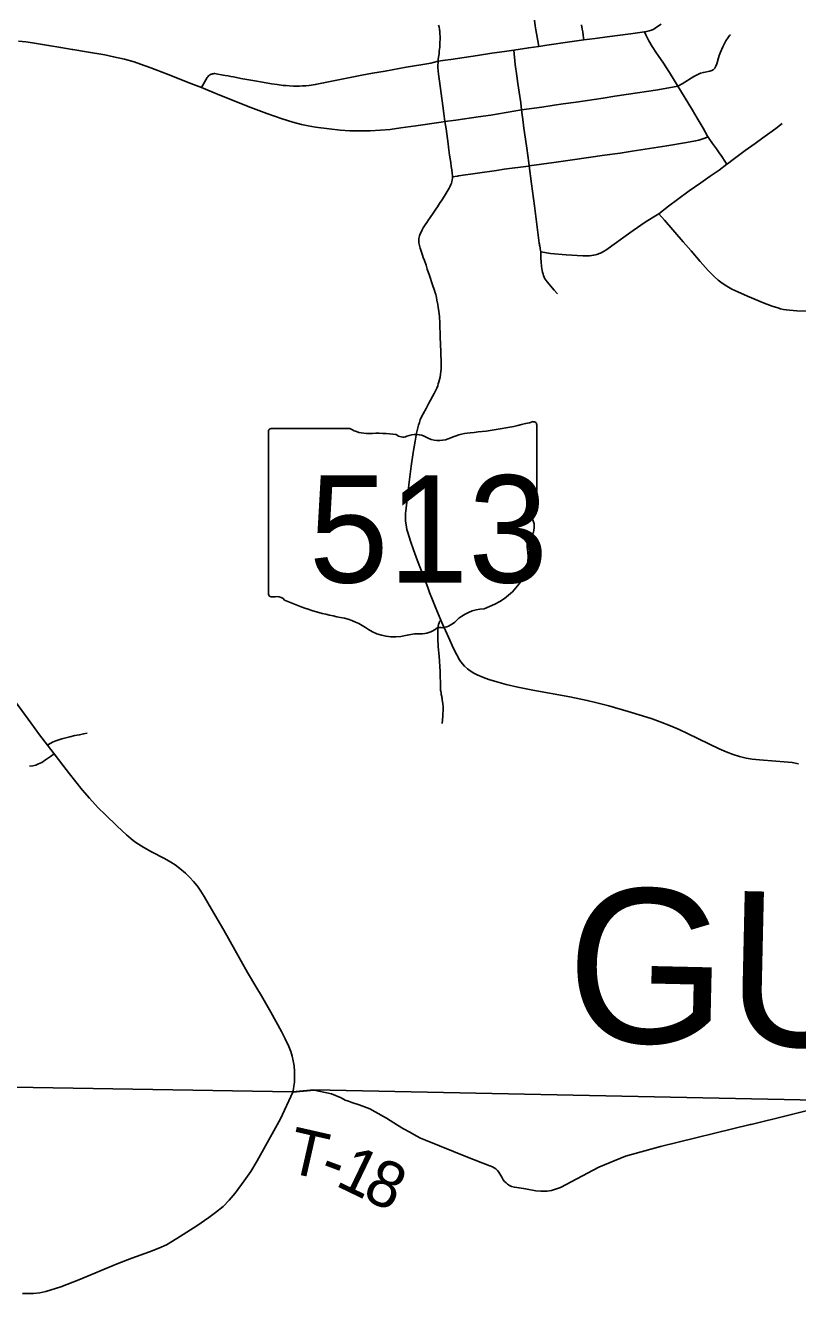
# Model space of a CAD drawing. Extents: x -10 to 158, y 8 to 33.
# Drawn here: x 149.672 to 150.622, y 29.874 to 31.433 of the extents above; entities that cross this region are included whole.
import ezdxf

# ---------------------------------------------------------------- set-up
doc = ezdxf.new("R2010")
doc.units = 0
for name, color, linetype in [('GM_X_City_Street', 7, 'Continuous'), ('GM_X_County_Road', 7, 'Continuous'), ('GM_X_County_Text', 7, 'Continuous'), ('GM_X_State_Location', 7, 'Continuous'), ('GM_X_State_Route', 7, 'Continuous'), ('GM_X_State_Shield', 7, 'Continuous'), ('GM_X_Township_Road', 7, 'Continuous'), ('GM_X_Township_Road_Text', 7, 'Continuous'), ('GM_X_Township_Text', 7, 'Continuous')]:
    doc.layers.add(name, color=color, linetype=linetype)

msp = doc.modelspace()

# ---------------------------------------------------------------- linework, layer by layer
at = {"layer": 'GM_X_City_Street'}
for points in [[(150.3034, 31.4071), (150.3022, 31.4138), (150.2999, 31.4276), (150.2992, 31.4322), (150.2982, 31.4391)], [(150.2726, 31.4023), (150.2912, 31.4054), (150.3034, 31.4071), (150.3133, 31.4086), (150.3416, 31.4126), (150.359, 31.415), (150.373, 31.4169), (150.3877, 31.4188), (150.4161, 31.4224), (150.4277, 31.424), (150.4334, 31.4249), (150.4344, 31.425), (150.4392, 31.4261), (150.4421, 31.427), (150.4448, 31.4283), (150.4484, 31.4305), (150.4538, 31.4345)], [(150.356, 31.4334), (150.3569, 31.4284), (150.3575, 31.4251), (150.3582, 31.4203), (150.3586, 31.4178), (150.359, 31.415)], [(150.5347, 31.2623), (150.5323, 31.266), (150.5286, 31.2716), (150.5276, 31.2731), (150.5262, 31.2751), (150.522, 31.2812), (150.5173, 31.2877), (150.5127, 31.2943), (150.5117, 31.2958), (150.511, 31.2969), (150.5056, 31.3067), (150.4984, 31.319), (150.4926, 31.3285), (150.4822, 31.3454), (150.4745, 31.3581), (150.4641, 31.3751), (150.456, 31.3876), (150.4483, 31.3988), (150.4428, 31.4071), (150.4388, 31.414), (150.4369, 31.4179), (150.4352, 31.4213), (150.4334, 31.4249)], [(150.4745, 31.3581), (150.4797, 31.3612), (150.494, 31.37), (150.4989, 31.3726), (150.5024, 31.374), (150.506, 31.3751), (150.5139, 31.3767), (150.5151, 31.3771), (150.5163, 31.3775), (150.5172, 31.378), (150.5179, 31.3784), (150.5187, 31.379), (150.5193, 31.3796), (150.5198, 31.3803), (150.5205, 31.3811), (150.5209, 31.3818), (150.5213, 31.3827), (150.5223, 31.3857), (150.5252, 31.3959), (150.5268, 31.4), (150.5297, 31.4067), (150.5336, 31.4139), (150.5362, 31.4181), (150.5382, 31.4205), (150.5391, 31.4213)], [(149.9154, 31.3718), (149.9179, 31.3714), (149.9216, 31.3708), (149.9247, 31.3702), (149.928, 31.3696), (149.937, 31.3677), (149.9542, 31.3649), (149.9639, 31.363), (149.9749, 31.3612), (149.9818, 31.3601), (149.989, 31.3592), (149.9927, 31.3589), (149.997, 31.3586), (150.0018, 31.3583), (150.0063, 31.3582), (150.0094, 31.3582), (150.0131, 31.3584), (150.0169, 31.3587), (150.0212, 31.3592), (150.0286, 31.3602), (150.0389, 31.3622), (150.0614, 31.3669), (150.0858, 31.3716), (150.0992, 31.374), (150.1145, 31.3766), (150.1402, 31.3814), (150.1586, 31.3844), (150.1707, 31.3866), (150.1737, 31.3873), (150.1796, 31.3887), (150.1885, 31.3901), (150.1954, 31.391), (150.228, 31.3959), (150.2458, 31.3987), (150.2612, 31.4007), (150.2726, 31.4023)], [(150.2823, 31.329), (150.2814, 31.3375), (150.2793, 31.351), (150.2777, 31.3615), (150.2764, 31.3707), (150.2746, 31.3849), (150.2726, 31.4023)], [(150.2823, 31.329), (150.3071, 31.3323), (150.3224, 31.3348), (150.3335, 31.3364), (150.3495, 31.3386), (150.3827, 31.3436), (150.3968, 31.3458), (150.411, 31.3478), (150.4497, 31.3537), (150.4745, 31.3581)], [(150.4512, 31.2014), (150.4632, 31.2105), (150.474, 31.2188), (150.4885, 31.2294), (150.5026, 31.2395), (150.5144, 31.2476), (150.5251, 31.255), (150.5347, 31.2623), (150.5355, 31.2629), (150.5424, 31.2681), (150.5574, 31.2791), (150.5694, 31.2879), (150.579, 31.2948), (150.5876, 31.3008), (150.5951, 31.3063), (150.6028, 31.3124)], [(150.1972, 31.2468), (150.2037, 31.2477), (150.2049, 31.2479), (150.2514, 31.2547), (150.2608, 31.256), (150.291, 31.26), (150.2917, 31.2601), (150.3218, 31.2643), (150.345, 31.2676), (150.3844, 31.2733), (150.4035, 31.276), (150.4183, 31.2782), (150.4342, 31.2807), (150.4609, 31.2847), (150.4851, 31.2888), (150.4964, 31.2909), (150.5005, 31.2918), (150.5029, 31.2925), (150.5063, 31.2937), (150.5096, 31.2949), (150.5117, 31.2958)], [(150.3267, 31.1029), (150.3225, 31.1075), (150.3136, 31.1178), (150.3124, 31.1192), (150.3114, 31.1208), (150.3106, 31.1222), (150.31, 31.1235), (150.3092, 31.1254), (150.3087, 31.127), (150.308, 31.1294), (150.3075, 31.1318), (150.3071, 31.1342), (150.3067, 31.1367), (150.3063, 31.1421), (150.3062, 31.1469), (150.306, 31.1544)]]:
    msp.add_lwpolyline(points, dxfattribs=at)
at = {"layer": 'GM_X_County_Road'}
msp.add_line((149.7075, 30.5376), (149.6992, 30.5485), dxfattribs=at)
for points in [[(149.6992, 30.5485), (149.6894, 30.5612), (149.6788, 30.5757), (149.6445, 30.623), (149.6371, 30.633), (149.6076, 30.673), (149.5895, 30.6975), (149.5808, 30.7096), (149.5718, 30.7229), (149.5683, 30.7288), (149.568, 30.7293)], [(150.0009, 30.1217), (150.0018, 30.126), (150.0023, 30.1294), (150.0029, 30.1342), (150.0032, 30.1405), (150.0031, 30.1474), (150.0026, 30.1542), (150.0016, 30.1604), (150.0003, 30.166), (149.9985, 30.172), (149.9962, 30.1778), (149.9917, 30.1874), (149.9872, 30.1963), (149.974, 30.2203), (149.9691, 30.2289), (149.9624, 30.2401), (149.9567, 30.2498), (149.9454, 30.269), (149.9299, 30.2967), (149.916, 30.3209), (149.9012, 30.3468), (149.8921, 30.3624), (149.8881, 30.3687), (149.8837, 30.3749), (149.879, 30.3807), (149.8744, 30.3858), (149.8689, 30.391), (149.8622, 30.3966), (149.8562, 30.4012), (149.851, 30.4046), (149.8434, 30.409), (149.8274, 30.4174), (149.8177, 30.4227), (149.8114, 30.4266), (149.8068, 30.4297), (149.8024, 30.4331), (149.7963, 30.4383), (149.7849, 30.4488), (149.7701, 30.463), (149.7618, 30.4713), (149.751, 30.4833), (149.7421, 30.4936), (149.7265, 30.5129), (149.7181, 30.5237), (149.7075, 30.5376)], [(149.6686, 29.8744), (149.682, 29.8743), (149.6899, 29.8754), (149.6971, 29.877), (149.7157, 29.8826), (149.7377, 29.8914), (149.7851, 29.9107), (149.8031, 29.918), (149.8249, 29.9255), (149.8363, 29.9301), (149.8455, 29.9344), (149.8585, 29.9422), (149.8706, 29.9497), (149.883, 29.9576), (149.8978, 29.9679), (149.906, 29.9738), (149.9154, 29.9812), (149.9229, 29.989), (149.9302, 29.9978), (149.9413, 30.0128), (149.9494, 30.0245), (149.9572, 30.0376), (149.9655, 30.0523), (149.9859, 30.0891), (150.0009, 30.1217)]]:
    msp.add_lwpolyline(points, dxfattribs=at)
at = {"layer": 'GM_X_State_Route'}
msp.add_line((150.2912, 31.2641), (150.2917, 31.2601), dxfattribs=at)
for points in [[(150.1803, 31.3939), (150.1808, 31.398), (150.1811, 31.4011), (150.1814, 31.4037), (150.1816, 31.4063), (150.1818, 31.4098), (150.1819, 31.4122), (150.1821, 31.4156), (150.1821, 31.4173), (150.1821, 31.4196), (150.1819, 31.4221), (150.1819, 31.4236), (150.1817, 31.4252), (150.1816, 31.4261), (150.1815, 31.4269), (150.1814, 31.4278), (150.1812, 31.4286), (150.1809, 31.4302), (150.1808, 31.431), (150.1806, 31.4318), (150.1803, 31.4333)], [(149.6635, 31.4133), (149.6727, 31.4125), (149.6807, 31.4114), (149.7007, 31.4082), (149.7157, 31.4056), (149.7295, 31.4033)], [(149.7295, 31.4033), (149.7305, 31.4032), (149.7471, 31.4004), (149.7697, 31.3965), (149.7807, 31.3943), (149.7939, 31.3912), (149.8059, 31.3879), (149.8135, 31.3854), (149.8264, 31.3809), (149.8455, 31.3734), (149.8755, 31.3615), (149.8887, 31.3564), (149.9013, 31.3512), (149.9132, 31.3462), (149.9147, 31.3457)], [(150.1801, 31.3731), (150.18, 31.3741), (150.1798, 31.3759), (150.1797, 31.378), (150.1795, 31.3805), (150.1795, 31.3824), (150.1795, 31.3846), (150.1796, 31.3866), (150.1796, 31.3877), (150.1796, 31.3887), (150.1799, 31.3908), (150.1803, 31.3939)], [(150.1952, 31.2644), (150.1938, 31.2734), (150.1926, 31.2832), (150.192, 31.2875), (150.1894, 31.3059), (150.1881, 31.3148), (150.1867, 31.3244), (150.1854, 31.3342), (150.1812, 31.3644), (150.1801, 31.3731)], [(149.9147, 31.3457), (149.9463, 31.3331), (149.9691, 31.3247), (149.9879, 31.3182), (150.001, 31.3141), (150.0118, 31.3112), (150.0197, 31.3095), (150.029, 31.3079), (150.0456, 31.3056), (150.0592, 31.3042), (150.0711, 31.3034), (150.0835, 31.3032), (150.0877, 31.3032)], [(150.1881, 31.3148), (150.2014, 31.3162), (150.229, 31.3204), (150.2444, 31.3225), (150.2823, 31.329)], [(150.2823, 31.329), (150.2843, 31.3141), (150.2853, 31.3064), (150.2871, 31.2929), (150.2887, 31.282), (150.2912, 31.2641)], [(150.0877, 31.3032), (150.096, 31.3034), (150.109, 31.3041), (150.1208, 31.3051), (150.1338, 31.3068), (150.1522, 31.3095), (150.1836, 31.3141), (150.1881, 31.3148)], [(150.1672, 31.1927), (150.17, 31.1968), (150.1734, 31.202), (150.177, 31.2072), (150.1789, 31.2099), (150.1815, 31.2141), (150.1849, 31.2194), (150.1882, 31.2247), (150.1934, 31.233), (150.1945, 31.2353), (150.1955, 31.2374), (150.1961, 31.2391), (150.1967, 31.2407), (150.1971, 31.243), (150.1972, 31.2445), (150.1973, 31.246), (150.1972, 31.2468), (150.1972, 31.2485), (150.197, 31.2508), (150.1965, 31.2553), (150.1959, 31.2594), (150.1952, 31.2644)], [(150.2917, 31.2601), (150.2946, 31.2382), (150.2981, 31.2111), (150.3041, 31.1654), (150.3042, 31.1642), (150.3044, 31.1629), (150.3046, 31.1614)], [(150.175, 30.9804), (150.1781, 30.9871), (150.1792, 30.9898), (150.1799, 30.9923), (150.1807, 30.9948), (150.1814, 30.9975), (150.1822, 31.0007), (150.1828, 31.0041), (150.1831, 31.0074), (150.1833, 31.0102), (150.1835, 31.0137), (150.1835, 31.0169), (150.183, 31.0323), (150.1823, 31.0496), (150.1818, 31.067), (150.1814, 31.0751), (150.1807, 31.0812), (150.1798, 31.0865), (150.1792, 31.0898), (150.1782, 31.0951), (150.1776, 31.0985), (150.1773, 31.1004), (150.1768, 31.1022), (150.1765, 31.1033), (150.1762, 31.1043), (150.1753, 31.1069), (150.1728, 31.114), (150.1689, 31.1257), (150.1664, 31.1333), (150.1648, 31.138), (150.1628, 31.1438), (150.1614, 31.1478), (150.1606, 31.1504), (150.1575, 31.1591), (150.1571, 31.1607), (150.1567, 31.1622), (150.1564, 31.1639), (150.1561, 31.1658), (150.156, 31.1671), (150.1559, 31.1684), (150.1559, 31.1697), (150.156, 31.1711), (150.1563, 31.1725), (150.1568, 31.1741), (150.1574, 31.1756), (150.1582, 31.1776), (150.1591, 31.1796), (150.1601, 31.1817), (150.1615, 31.184), (150.163, 31.1866), (150.1666, 31.1919), (150.1672, 31.1927)], [(150.306, 31.1544), (150.3178, 31.1526), (150.337, 31.151), (150.3575, 31.1498), (150.3632, 31.1496), (150.3657, 31.1497), (150.3685, 31.15), (150.3709, 31.1504), (150.3732, 31.1509), (150.3748, 31.1513), (150.3763, 31.1518), (150.3779, 31.1524), (150.3794, 31.153), (150.3831, 31.155), (150.3858, 31.1567), (150.399, 31.1661), (150.408, 31.1726), (150.4196, 31.1809), (150.4345, 31.191), (150.4429, 31.1963), (150.4512, 31.2014)], [(150.4512, 31.2014), (150.4579, 31.1937), (150.481, 31.167), (150.4908, 31.1558), (150.5021, 31.1427), (150.5119, 31.1316), (150.5191, 31.1241), (150.5241, 31.1196), (150.5289, 31.116), (150.5346, 31.1123), (150.541, 31.1088), (150.5482, 31.1053), (150.5601, 31.1002), (150.5807, 31.0917), (150.5904, 31.0879), (150.5974, 31.0856), (150.6006, 31.0847), (150.6045, 31.0838), (150.608, 31.0832), (150.6117, 31.0827), (150.6164, 31.0823), (150.621, 31.082), (150.637, 31.0816)], [(150.3046, 31.1614), (150.305, 31.1596), (150.3052, 31.1584), (150.3056, 31.1566), (150.306, 31.1544)], [(150.6229, 30.5254), (150.615, 30.5269), (150.6053, 30.5279), (150.5948, 30.5287), (150.575, 30.5302), (150.5657, 30.5313), (150.5584, 30.5325), (150.5505, 30.5343), (150.5427, 30.5367), (150.534, 30.54), (150.5254, 30.5437), (150.5125, 30.5499), (150.4864, 30.5628), (150.4763, 30.5675), (150.4655, 30.5721), (150.4529, 30.577), (150.4429, 30.5805), (150.4312, 30.5844), (150.4134, 30.5898), (150.3895, 30.5966), (150.3734, 30.6009), (150.3631, 30.6033), (150.3418, 30.6075), (150.296, 30.6159), (150.2777, 30.6196), (150.2632, 30.623), (150.2517, 30.6261), (150.2422, 30.629), (150.2357, 30.6313), (150.2276, 30.6346), (150.2237, 30.6366), (150.2189, 30.6396), (150.2159, 30.642), (150.2121, 30.6453), (150.2078, 30.6507), (150.2061, 30.6533), (150.2028, 30.6594), (150.1988, 30.667), (150.1923, 30.6812), (150.1886, 30.6892), (150.1853, 30.6963), (150.1829, 30.7018), (150.177, 30.7165), (150.1728, 30.7269), (150.1692, 30.7361), (150.167, 30.7419), (150.1637, 30.7506), (150.1542, 30.7749), (150.1493, 30.7883), (150.1457, 30.7989), (150.1424, 30.8096), (150.1414, 30.8132), (150.1407, 30.8161), (150.1402, 30.8189), (150.1399, 30.8213), (150.1396, 30.824), (150.1395, 30.827), (150.1394, 30.8288), (150.1395, 30.8313), (150.1396, 30.8334), (150.1398, 30.8357), (150.1416, 30.8505), (150.1422, 30.8558), (150.1427, 30.8603), (150.1431, 30.864), (150.1437, 30.8683), (150.1467, 30.891), (150.1492, 30.9079), (150.1515, 30.922), (150.1533, 30.9318), (150.1549, 30.9384), (150.1557, 30.9415), (150.1567, 30.945), (150.1578, 30.948), (150.159, 30.9509), (150.1611, 30.9554), (150.1648, 30.9622), (150.1684, 30.9685), (150.175, 30.9804)]]:
    msp.add_lwpolyline(points, dxfattribs=at)
at = {"layer": 'GM_X_State_Shield'}
for p, q in [((150.3009, 30.8378), (150.3009, 30.9425)), ((149.9713, 30.9341), (149.9713, 30.734)), ((150.071, 30.9375), (149.9745, 30.9375)), ((150.3008, 30.8378), (150.3009, 30.8378))]:
    msp.add_line(p, q, dxfattribs=at)
for centre, major_axis, start_param, end_param in [((150.1834, 31.2104), (0.3495, 0), 4.814394, 5.042369), ((150.2972, 30.9429), (0.00367, 0), 6.141152, 7.989035), ((149.975, 30.9345), (0.00382, 0), 1.712693, 3.28349), ((150.094, 30.9608), (0.037, 0), 4.042523, 4.731795), ((150.1063, 30.8252), (0.133, 0), 1.404758, 1.657858), ((150.1365, 30.9355), (0.0107, 0), 3.836095, 5.185415), ((150.1522, 30.9124), (0.0222, 0), 0.950623, 2.079405), ((150.1808, 30.9441), (0.0267, 0), 4.081561, 5.145723), ((150.228, 30.8764), (0.0703, 0), 1.699011, 2.107814), ((150.3, 30.8301), (0.00568, 0), 1.883978, 3.671073), ((150.2969, 30.8374), (0.00393, 0), 5.05454, 6.418171), ((150.2639, 30.8169), (0.0341, 0), 5.934695, 6.695948), ((150.314, 30.794), (0.0248, 0), 2.387724, 3.262537), ((150.203, 30.7807), (0.0874, 0), 5.101752, 6.440018), ((149.9751, 30.7335), (0.00385, 0), 3.00124, 4.508301), ((149.9757, 30.754), (0.0294, 0), 4.665946, 4.897461), ((149.9817, 30.7224), (0.0106, 0), 0.519207, 1.627899), ((150.1155, 30.9022), (0.2524, 0), 4.195997, 4.488961), ((150.0403, 30.6441), (0.079, 0), 0.823519, 1.323587), ((150.2399, 30.6778), (0.0479, 0), 1.647645, 2.488434), ((150.1257, 30.7214), (0.0501, 0), 4.026481, 4.996735), ((150.1583, 30.7064), (0.0267, 0), 4.691044, 5.507374), ((150.1824, 30.6871), (0.00752, 0), 1.147584, 2.315152), ((150.1792, 30.7146), (0.0282, 0), 4.937069, 5.64225), ((150.1546, 30.6522), (0.0412, 0), 1.495662, 1.94098)]:
    msp.add_ellipse(centre, major_axis=major_axis, ratio=0.8, start_param=start_param, end_param=end_param, dxfattribs=at)
at = {"layer": 'GM_X_Township_Road'}
msp.add_line((150.5645, 30.0822), (150.6814, 30.1109), dxfattribs=at)
for points in [[(149.8887, 31.3564), (149.8958, 31.3688), (149.8966, 31.3698), (149.8974, 31.3707), (149.8981, 31.3714), (149.8989, 31.3719), (149.8996, 31.3724), (149.9005, 31.3728), (149.9013, 31.3731), (149.9022, 31.3734), (149.903, 31.3735), (149.9041, 31.3736), (149.9052, 31.3736), (149.9066, 31.3734), (149.9154, 31.3718)], [(150.1846, 30.5751), (150.1853, 30.5841), (150.1856, 30.5876), (150.1858, 30.5902), (150.1858, 30.5931), (150.1857, 30.5958), (150.1854, 30.5992), (150.1851, 30.6021), (150.1848, 30.604), (150.1845, 30.6056), (150.1843, 30.6069), (150.1841, 30.608), (150.1839, 30.6094), (150.1836, 30.6107), (150.1833, 30.6127), (150.183, 30.6146), (150.1828, 30.616), (150.1827, 30.6176), (150.1827, 30.6192), (150.1826, 30.6208), (150.1826, 30.6221), (150.1826, 30.6241), (150.1824, 30.634), (150.1822, 30.6388), (150.1809, 30.6575), (150.1798, 30.6692), (150.1793, 30.6792), (150.1792, 30.6873), (150.1794, 30.69), (150.1796, 30.6928), (150.1798, 30.6947), (150.1802, 30.6965), (150.1808, 30.6985), (150.181, 30.6994), (150.1813, 30.7), (150.1818, 30.7007), (150.1823, 30.7013), (150.1829, 30.7018)], [(149.6992, 30.5485), (149.7006, 30.5493), (149.7055, 30.5518), (149.7095, 30.5536), (149.7132, 30.555), (149.7169, 30.556), (149.7269, 30.5585), (149.7329, 30.56), (149.7385, 30.5612), (149.7438, 30.5622), (149.748, 30.563)], [(149.6774, 30.5226), (149.6811, 30.5231), (149.6848, 30.5239), (149.6883, 30.5252), (149.6922, 30.5272), (149.6969, 30.5302), (149.703, 30.5345), (149.7075, 30.5376)], [(150.0009, 30.1217), (150.0271, 30.1242), (150.0485, 30.1197), (150.0605, 30.1147), (150.0655, 30.1122), (150.0693, 30.1106), (150.0734, 30.109), (150.0825, 30.1061), (150.0892, 30.104), (150.0957, 30.1012), (150.1022, 30.0978), (150.1161, 30.09), (150.1297, 30.0814), (150.1371, 30.077), (150.1449, 30.0725), (150.1528, 30.068), (150.1579, 30.0654), (150.164, 30.0629), (150.1813, 30.0557), (150.1988, 30.0488), (150.2139, 30.043), (150.223, 30.0393), (150.2345, 30.0348), (150.2467, 30.0299), (150.2507, 30.0277), (150.2529, 30.0257), (150.2545, 30.0234), (150.2579, 30.0174), (150.2595, 30.0143), (150.2613, 30.0121), (150.2632, 30.0103), (150.2652, 30.0087), (150.2676, 30.0072), (150.27, 30.0061), (150.2735, 30.0051), (150.2792, 30.0041), (150.287, 30.003), (150.2998, 30.0007), (150.306, 30.0001), (150.3136, 30.0002), (150.3192, 30.001), (150.3302, 30.0048), (150.3772, 30.0298), (150.4103, 30.0432), (150.4533, 30.055), (150.5635, 30.082), (150.5645, 30.0822)]]:
    msp.add_lwpolyline(points, dxfattribs=at)
at = {"layer": 'GM_X_Township_Text'}
msp.add_lwpolyline([(148.6038, 30.1399), (149.1083, 30.1364), (149.1287, 30.1368), (149.2397, 30.1351), (150.0007, 30.1222), (150.0269, 30.1247), (150.6451, 30.1119), (150.6811, 30.1115), (151.1372, 30.1057), (152.063, 30.0899), (152.8656, 30.0723), (153.1825, 30.071), (153.2474, 30.0684), (153.3319, 30.0657), (153.3945, 30.0654), (153.6154, 30.0623), (153.6996, 30.0615), (153.7013, 30.1642), (153.702, 30.2085), (153.7021, 30.212), (153.7282, 31.2273), (153.7348, 31.8623)], dxfattribs=at)

# ---------------------------------------------------------------- texts
at = {"layer": 'GM_X_County_Text'}
msp.add_text('GUERNSEY COUNTY', height=0.189394, rotation=358.7038, dxfattribs=at).set_placement((150.336, 30.1845))
at = {"layer": 'GM_X_State_Location'}
for s, p in [('s', (150.1324, 30.8207)), ('r', (150.1323, 30.8207))]:
    msp.add_text(s, height=0.000189, dxfattribs=at).set_placement(p)
msp.add_text('513', height=0.000189, rotation=0, dxfattribs=at).set_placement((150.0655, 30.8069))
at = {"layer": 'GM_X_State_Shield'}
msp.add_text('513', height=0.13184, dxfattribs=at).set_placement((150.0207, 30.7481))
at = {"layer": 'GM_X_Township_Road_Text'}
for s, rotation, p in [('T', 347.2039, (149.9917, 30.0242)), ('-', 339.5801, (150.0312, 30.0154)), ('1', 334.2402, (150.0518, 30.0078)), ('8', 335.6277, (150.0847, 29.9919))]:
    msp.add_text(s, height=0.0568, rotation=rotation, dxfattribs=at).set_placement(p)

doc.saveas('drawing.dxf')
